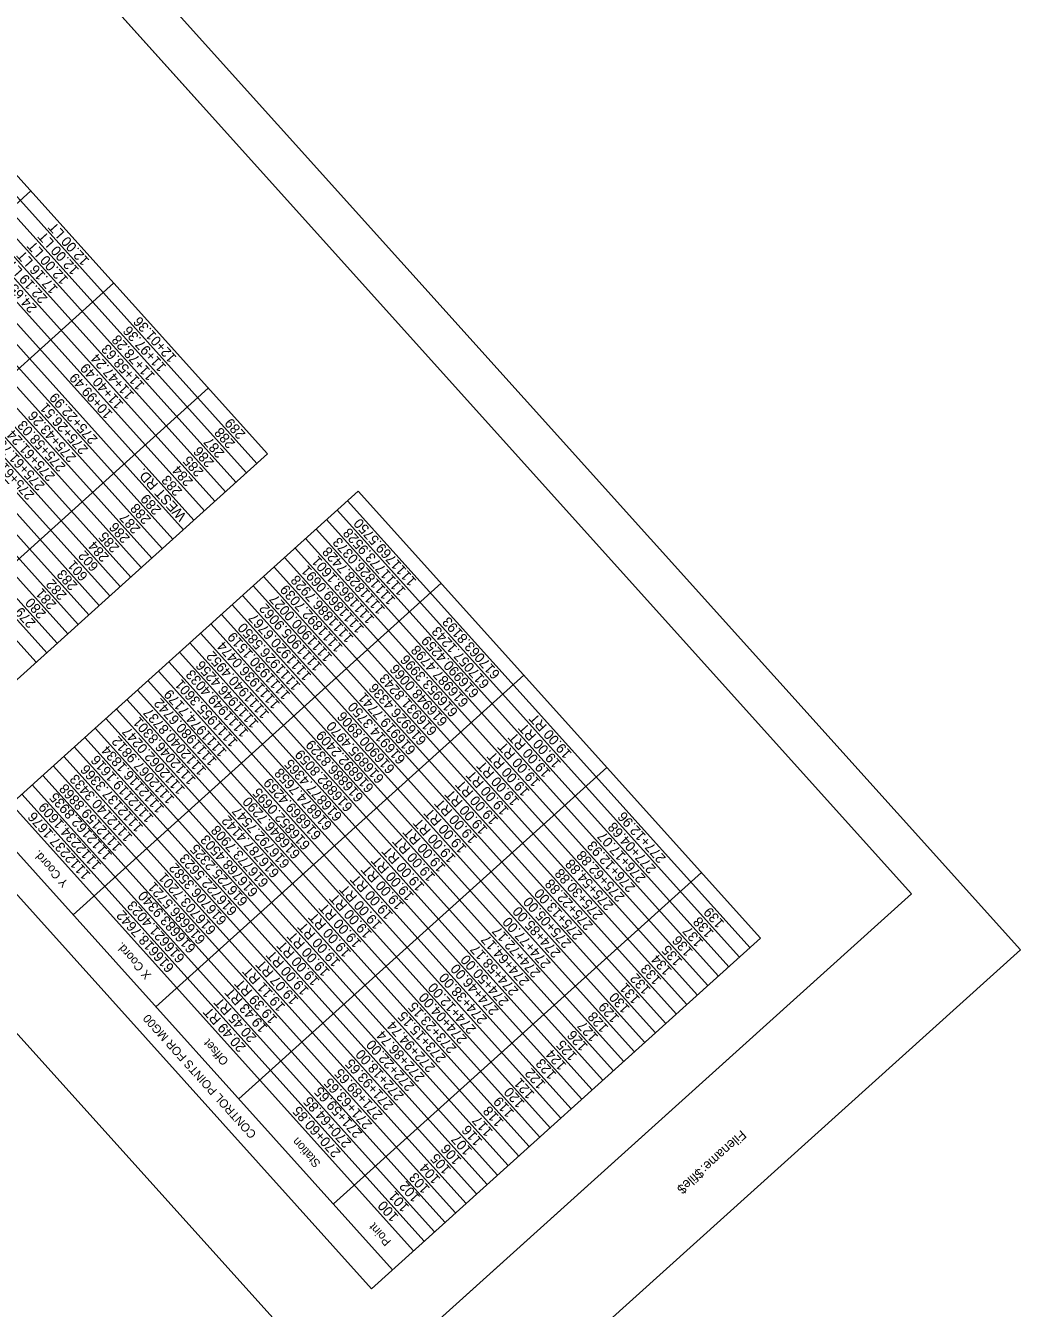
# Model space of a CAD drawing. Extents: x 1111534 to 1112511, y 616515 to 617559.
# Drawn here: x 1112159.5 to 1112511, y 616756 to 617209.1 of the extents above; entities that cross this region are included whole.
import ezdxf

# ---------------------------------------------------------------- set-up
doc = ezdxf.new("R2010")
doc.units = 0
for name, color, linetype in [('ANNOTATION', 7, 'Continuous'), ('BORDER', 7, 'Continuous'), ('CLIPS', 7, 'Continuous'), ('H_V CONTROLS', 7, 'Continuous'), ('PLOT BOUNDARY', 7, 'Continuous')]:
    doc.layers.add(name, color=color, linetype=linetype)

msp = doc.modelspace()

# ---------------------------------------------------------------- linework, layer by layer
at = {"layer": 'BORDER'}
for p, q in [((1112472.55, 616902.44), (1111937.25, 617496.96)), ((1112082.4, 616551.15), (1112472.55, 616902.44))]:
    msp.add_line(p, q, dxfattribs=at)
at = {"layer": 'CLIPS'}
msp.add_lwpolyline([(1112472.55, 616902.44), (1111970.7, 617459.8), (1111771.54, 617280.48), (1112273.39, 616723.12)], close=True, dxfattribs=at)
at = {"layer": 'H_V CONTROLS'}
for p, q in [((1112244.92, 617057.82), (1112102.73, 617215.74)), ((1112241.2, 617054.48), (1112099.01, 617212.4)), ((1112233.77, 617047.79), (1112091.58, 617205.71)), ((1112237.49, 617051.13), (1112095.3, 617209.05)), ((1112230.06, 617044.44), (1112087.87, 617202.36)), ((1112226.34, 617041.1), (1112084.15, 617199.01)), ((1112218.91, 617034.4), (1112076.72, 617192.32)), ((1112222.62, 617037.75), (1112080.43, 617195.67)), ((1112215.19, 617031.06), (1112073, 617188.98)), ((1112207.76, 617024.37), (1112065.57, 617182.29)), ((1112211.48, 617027.71), (1112069.29, 617185.63)), ((1112204.05, 617021.02), (1112061.86, 617178.94)), ((1112200.33, 617017.68), (1112058.14, 617175.59)), ((1112192.9, 617010.99), (1112050.71, 617168.9)), ((1112196.61, 617014.33), (1112054.42, 617172.25)), ((1112189.18, 617007.64), (1112046.99, 617165.56)), ((1112185.47, 617004.29), (1112043.28, 617162.21)), ((1112178.04, 616997.6), (1112035.85, 617155.52)), ((1112181.75, 617000.95), (1112039.56, 617158.87)), ((1112174.32, 616994.26), (1112032.13, 617152.18)), ((1112042.37, 617043.66), (1112161.28, 617150.72)), ((1112170.6, 616990.91), (1112028.41, 617148.83)), ((1112163.17, 616984.22), (1112020.98, 617142.14)), ((1112166.89, 616987.57), (1112024.7, 617145.48)), ((1112071.65, 617011.14), (1112190.55, 617118.2)), ((1112105.11, 616973.99), (1112224.01, 617081.05)), ((1112118.58, 616944.07), (1112244.92, 617057.82)), ((1112139.49, 616920.85), (1112276.98, 617044.64)), ((1112419.17, 616886.72), (1112276.98, 617044.64)), ((1112419.17, 616886.72), (1112276.98, 617044.64)), ((1112411.73, 616880.03), (1112269.54, 617037.95)), ((1112415.45, 616883.37), (1112273.26, 617041.29)), ((1112408.02, 616876.68), (1112265.83, 617034.6)), ((1112404.3, 616873.34), (1112262.11, 617031.26)), ((1112396.87, 616866.65), (1112254.68, 617024.56)), ((1112400.59, 616869.99), (1112258.4, 617027.91)), ((1112393.16, 616863.3), (1112250.97, 617021.22)), ((1112385.72, 616856.61), (1112243.53, 617014.53)), ((1112389.44, 616859.95), (1112247.25, 617017.87)), ((1112176.2, 616895.03), (1112306.25, 617012.13)), ((1112382.01, 616853.26), (1112239.82, 617011.18)), ((1112378.29, 616849.92), (1112236.1, 617007.84)), ((1112370.86, 616843.23), (1112228.67, 617001.14)), ((1112374.58, 616846.57), (1112232.39, 617004.49)), ((1112367.15, 616839.88), (1112224.96, 616997.8)), ((1112363.43, 616836.54), (1112221.24, 616994.45)), ((1112356, 616829.84), (1112213.81, 616987.76)), ((1112359.71, 616833.19), (1112217.52, 616991.11)), ((1112352.28, 616826.5), (1112210.09, 616984.42)), ((1112205.47, 616862.52), (1112335.53, 616979.61)), ((1112348.57, 616823.15), (1112206.38, 616981.07)), ((1112341.14, 616816.46), (1112198.95, 616974.38)), ((1112344.85, 616819.81), (1112202.66, 616977.73)), ((1112337.42, 616813.12), (1112195.23, 616971.03)), ((1112333.7, 616809.77), (1112191.51, 616967.69)), ((1112326.27, 616803.08), (1112184.08, 616961)), ((1112329.99, 616806.42), (1112187.8, 616964.34)), ((1112322.56, 616799.73), (1112180.37, 616957.65)), ((1112318.84, 616796.39), (1112176.65, 616954.31)), ((1112311.41, 616789.7), (1112169.22, 616947.61)), ((1112315.13, 616793.04), (1112172.94, 616950.96)), ((1112234.75, 616830), (1112364.8, 616947.1)), ((1112307.69, 616786.35), (1112165.5, 616944.27)), ((1112300.26, 616779.66), (1112158.07, 616937.58)), ((1112303.98, 616783), (1112161.79, 616940.92)), ((1112296.55, 616776.31), (1112154.36, 616934.23)), ((1112289.12, 616769.62), (1112146.93, 616927.54)), ((1112281.68, 616762.93), (1112139.49, 616920.85)), ((1112268.21, 616792.85), (1112398.26, 616909.94)), ((1112281.68, 616762.93), (1112419.17, 616886.72))]:
    msp.add_line(p, q, dxfattribs=at)
at = {"layer": 'PLOT BOUNDARY'}
msp.add_lwpolyline([(1112510.99, 616882.61), (1111942.23, 617514.28), (1111533.5, 617146.26), (1112102.26, 616514.59)], close=True, dxfattribs=at)

# ---------------------------------------------------------------- texts
at = {"layer": 'ANNOTATION'}
for s, height, p in [('12.00 LT', 3.516, (1112182.17, 617126.24)), ('12.00 LT', 3.516, (1112174.76, 617119.57)), ('12.00 LT', 3.516, (1112178.52, 617122.95)), ('17.16 LT', 3.516, (1112171.07, 617116.25)), ('22.19 LT', 3.516, (1112167.38, 617112.92)), ('24.65 LT', 3.516, (1112163.63, 617109.54)), ('12+01.36', 3.516, (1112213, 617092)), ('11+97.36', 3.516, (1112209.35, 617088.71)), ('11+58.63', 3.516, (1112201.69, 617082.24)), ('11+78.28', 3.516, (1112205.38, 617085.56)), ('11+47.24', 3.516, (1112198.01, 617078.92)), ('11+40.49', 3.516, (1112194.25, 617075.54)), ('10+99.49', 3.516, (1112190.43, 617072.1)), ('275+22.99', 3.516, (1112185.11, 617063.17)), ('275+26.51', 3.516, (1112181.73, 617059.57)), ('275+58.03', 3.516, (1112173.8, 617053.41)), ('275+43.26', 3.516, (1112177.51, 617056.75)), ('289', 3.516, (1112237.35, 617064.96)), ('275+61.24', 3.516, (1112170.08, 617050.06)), ('288', 3.516, (1112233.69, 617061.67)), ('275+61.73', 3.516, (1112166.43, 617046.77)), ('286', 3.516, (1112226.25, 617054.97)), ('287', 3.516, (1112229.94, 617058.29)), ('275+61.43', 3.45, (1112162.74, 617043.45)), ('285', 3.516, (1112222.56, 617051.64)), ('WEST RD.', 3.516, (1112216.49, 617036.01)), ('284', 3.516, (1112218.81, 617048.26)), ('283', 3.516, (1112214.99, 617044.83)), ('289', 3.516, (1112207.61, 617038.18)), ('288', 3.516, (1112203.96, 617034.89)), ('286', 3.516, (1112196.51, 617028.19)), ('287', 3.516, (1112200.22, 617031.53)), ('1111769.5750', 3.5156, (1112297.78, 617013.03)), ('285', 3.516, (1112192.79, 617024.84)), ('1111826.0373', 3.5156, (1112290.37, 617006.36)), ('1111773.9528', 3.5156, (1112294.03, 617009.65)), ('602', 3.45, (1112185.45, 617018.23)), ('284', 3.516, (1112189.14, 617021.55)), ('1111828.7428', 3.5156, (1112286.69, 617003.04)), ('601', 3.45, (1112181.66, 617014.81)), ('1111863.1601', 3.5156, (1112282.93, 616999.66)), ('283', 3.516, (1112178, 617011.52)), ('1111886.7928', 3.5156, (1112275.52, 616992.99)), ('1111869.0691', 3.5156, (1112279.24, 616996.34)), ('281', 3.516, (1112170.53, 617004.79)), ('282', 3.516, (1112174.19, 617008.09)), ('1111892.7039', 3.5156, (1112271.78, 616989.62)), ('280', 3.516, (1112166.87, 617001.5)), ('1111900.0027', 3.5156, (1112268.03, 616986.24)), ('279', 3.516, (1112163.22, 616998.21)), ('1111920.6767', 3.5156, (1112260.64, 616979.58)), ('1111905.9062', 3.5156, (1112264.39, 616982.96)), ('1111926.5850', 3.5156, (1112256.82, 616976.14)), ('617057.1243', 3.5156, (1112323.6, 616976.81)), ('617063.8193', 3.5156, (1112327.35, 616980.19)), ('1111930.1519', 3.5156, (1112253.19, 616972.88)), ('616990.4259', 3.5156, (1112319.94, 616973.52)), ('1111940.4952', 3.5156, (1112245.72, 616966.15)), ('1111936.0474', 3.5156, (1112249.54, 616969.59)), ('616987.4798', 3.5156, (1112316.25, 616970.2)), ('1111946.4256', 3.5156, (1112242, 616962.8)), ('616948.0066', 3.5156, (1112308.81, 616963.5)), ('616953.3996', 3.5156, (1112312.5, 616966.82)), ('1111955.3601', 3.5156, (1112234.62, 616956.16)), ('1111949.4033', 3.5156, (1112238.44, 616959.6)), ('616931.8243', 3.5156, (1112305.09, 616960.15)), ('1111974.7179', 3.5156, (1112230.74, 616952.66)), ('616926.4336', 3.5156, (1112301.35, 616956.78)), ('1111980.6742', 3.5156, (1112227.21, 616949.49)), ('616914.3750', 3.5156, (1112293.96, 616950.12)), ('616919.7741', 3.5156, (1112297.6, 616953.4)), ('1112046.8301', 3.5156, (1112219.8, 616942.81)), ('1112040.8737', 3.5156, (1112223.49, 616946.13)), ('616900.8906', 3.5156, (1112290.2, 616946.74)), ('19.00 RT', 3.516, (1112352.65, 616952.09)), ('1112062.0247', 3.5156, (1112216.01, 616939.4)), ('616895.4970', 3.5156, (1112286.39, 616943.31)), ('19.00 RT', 3.516, (1112348.9, 616948.71)), ('1112067.9812', 3.5156, (1112212.29, 616936.05)), ('616886.8329', 3.5156, (1112279.11, 616936.75)), ('616892.2409', 3.5156, (1112282.76, 616940.04)), ('19.00 RT', 3.516, (1112345.24, 616945.42)), ('1112119.1616', 3.5156, (1112204.9, 616929.4)), ('1112116.1834', 3.5156, (1112208.65, 616932.78)), ('616882.8059', 3.5156, (1112275.29, 616933.31)), ('19.00 RT', 3.516, (1112337.8, 616938.72)), ('19.00 RT', 3.516, (1112341.55, 616942.1)), ('1112137.3366', 3.5156, (1112201.21, 616926.07)), ('616874.7658', 3.5156, (1112268.01, 616926.76)), ('616877.4365', 3.5156, (1112271.57, 616929.96)), ('19.00 RT', 3.516, (1112334.11, 616935.4)), ('1112140.3433', 3.5156, (1112197.42, 616922.67)), ('616869.4259', 3.5156, (1112264.19, 616923.32)), ('19.00 RT', 3.516, (1112326.65, 616928.68)), ('19.00 RT', 3.516, (1112330.39, 616932.05)), ('1112162.8935', 3.5156, (1112190.26, 616916.21)), ('1112159.8868', 3.5156, (1112193.7, 616919.31)), ('616852.0695', 3.5156, (1112260.3, 616919.82)), ('19.00 RT', 3.516, (1112322.9, 616925.3)), ('1112234.1609', 3.5156, (1112186.41, 616912.75)), ('616846.7290', 3.5156, (1112256.78, 616916.65)), ('19.00 RT', 3.516, (1112319.26, 616922.03)), ('1112237.1676', 3.5156, (1112182.62, 616909.34)), ('616787.4142', 3.5156, (1112249.37, 616909.97)), ('616792.7547', 3.5156, (1112253.06, 616913.3)), ('19.00 RT', 3.516, (1112311.69, 616915.21)), ('19.00 RT', 3.516, (1112315.5, 616918.65)), ('277+12.96', 3.516, (1112385.92, 616915.15)), ('616773.7908', 3.5156, (1112245.58, 616906.57)), ('19.00 RT', 3.516, (1112308.06, 616911.94)), ('277+04.68', 3.516, (1112382.44, 616911.46)), ('616725.2325', 3.5156, (1112238.22, 616899.94)), ('616768.4503', 3.5156, (1112241.86, 616903.21)), ('19.00 RT', 3.516, (1112304.41, 616908.65)), ('276+12.93', 3.516, (1112375.1, 616904.85)), ('276+17.07', 3.516, (1112378.79, 616908.17)), ('616722.5623', 3.5156, (1112234.47, 616896.56)), ('19.00 RT', 3.516, (1112296.87, 616901.86)), ('19.00 RT', 3.516, (1112300.59, 616905.21)), ('275+62.88', 3.516, (1112371.34, 616901.47)), ('616706.3582', 3.5156, (1112230.78, 616893.24)), ('19.00 RT', 3.516, (1112293.31, 616898.66)), ('275+30.88', 3.516, (1112363.66, 616895.1)), ('275+54.88', 3.516, (1112367.38, 616898.45)), ('616686.5721', 3.5156, (1112223.27, 616886.48)), ('616703.7201', 3.5156, (1112226.99, 616889.83)), ('19.00 RT', 3.516, (1112289.49, 616895.22)), ('275+22.88', 3.516, (1112360.2, 616891.43)), ('616683.9340', 3.5156, (1112219.83, 616883.37)), ('19.00 RT', 3.516, (1112282.08, 616888.55)), ('19.00 RT', 3.516, (1112285.6, 616891.72)), ('275+13.00', 3.516, (1112356.44, 616888.05)), ('616618.7642', 3.5156, (1112212.19, 616876.5)), ('616621.4023', 3.5156, (1112215.97, 616879.91)), ('19.00 RT', 3.516, (1112278.36, 616885.2)), ('274+85.00', 3.516, (1112348.77, 616881.7)), ('275+05.00', 3.516, (1112352.53, 616885.08)), ('139', 3.516, (1112406.59, 616892.19)), ('19.00 RT', 3.516, (1112274.67, 616881.88)), ('274+77.00', 3.516, (1112345.23, 616877.95)), ('138', 3.516, (1112402.84, 616888.81)), ('19.00 RT', 3.516, (1112267.16, 616875.12)), ('19.00 RT', 3.516, (1112270.88, 616878.47)), ('274+72.17', 3.516, (1112341.6, 616874.69)), ('137', 3.516, (1112399.18, 616885.51)), ('19.00 RT', 3.516, (1112263.52, 616871.84)), ('274+58.17', 3.516, (1112333.85, 616868.27)), ('274+64.17', 3.516, (1112337.67, 616871.71)), ('135', 3.516, (1112391.74, 616878.81)), ('136', 3.516, (1112395.49, 616882.19)), ('19.07 RT', 3.516, (1112256.08, 616865.14)), ('19.00 RT', 3.516, (1112259.77, 616868.46)), ('274+50.00', 3.516, (1112330.41, 616864.61)), ('134', 3.516, (1112388.05, 616875.49)), ('19.11 RT', 3.516, (1112251.39, 616862.73)), ('274+38.00', 3.516, (1112322.76, 616858.27)), ('274+46.00', 3.516, (1112326.85, 616861.41)), ('132', 3.516, (1112380.59, 616868.78)), ('133', 3.516, (1112384.33, 616872.14)), ('19.39 RT', 3.516, (1112248.57, 616858.38)), ('274+12.00', 3.516, (1112318.87, 616854.78)), ('131', 3.516, (1112376.84, 616865.4)), ('20.45 RT', 3.516, (1112241.27, 616851.81)), ('19.43 RT', 3.516, (1112245.13, 616855.28)), ('274+04.00', 3.516, (1112315.62, 616851.3)), ('130', 3.516, (1112373.2, 616862.12)), ('20.49 RT', 3.516, (1112237.49, 616848.4)), ('273+15.15', 3.516, (1112308.21, 616844.62)), ('273+23.15', 3.516, (1112311.9, 616847.94)), ('128', 3.516, (1112365.63, 616855.3)), ('129', 3.516, (1112369.45, 616858.74)), ('272+94.74', 3.516, (1112304.42, 616841.21)), ('127', 3.516, (1112362, 616852.04)), ('272+86.74', 3.516, (1112300.7, 616837.86)), ('126', 3.516, (1112358.35, 616848.74)), ('272+18.00', 3.516, (1112293.31, 616831.21)), ('272+22.00', 3.516, (1112297.06, 616834.59)), ('124', 3.516, (1112350.81, 616841.96)), ('125', 3.516, (1112354.53, 616845.31)), ('271+93.65', 3.516, (1112289.62, 616827.88)), ('123', 3.516, (1112347.25, 616838.75)), ('271+89.65', 3.516, (1112285.83, 616824.47)), ('122', 3.516, (1112343.43, 616835.31)), ('271+59.65', 3.516, (1112278.67, 616818.02)), ('271+63.65', 3.516, (1112282.11, 616821.12)), ('120', 3.516, (1112336.02, 616828.64)), ('121', 3.516, (1112339.54, 616831.82)), ('270+64.85', 3.516, (1112274.82, 616814.56)), ('119', 3.516, (1112332.3, 616825.29)), ('270+60.85', 3.516, (1112271.03, 616811.15)), ('118', 3.516, (1112328.61, 616821.97)), ('116', 3.516, (1112321.1, 616815.21)), ('117', 3.516, (1112324.82, 616818.56)), ('107', 3.516, (1112317.46, 616811.93)), ('106', 3.516, (1112313.71, 616808.55)), ('104', 3.516, (1112306.23, 616801.82)), ('105', 3.516, (1112310.02, 616805.23)), ('103', 3.516, (1112302.51, 616798.47)), ('101', 3.516, (1112295.22, 616791.9)), ('102', 3.516, (1112299.07, 616795.37)), ('100', 3.516, (1112291.43, 616788.49))]:
    msp.add_text(s, height=height, rotation=132, dxfattribs=at).set_placement(p)
at = {"layer": 'BORDER'}
for s, p in [('Filename:', (1112412.31, 616819.17)), ('$file$', (1112397.34, 616805.7))]:
    msp.add_text(s, height=3.348, rotation=222, dxfattribs=at).set_placement(p)
at = {"layer": 'H_V CONTROLS'}
for s, p in [('Y Coord.', (1112174.73, 616906.37)), ('X Coord.', (1112204.01, 616873.86)), ('CONTROL POINTS FOR MG00', (1112241.2, 616817.61)), ('Offset', (1112231.39, 616843.44)), ('Station', (1112263.91, 616807.33)), ('Point', (1112288.81, 616779.68))]:
    msp.add_text(s, height=3, rotation=132, dxfattribs=at).set_placement(p)

doc.saveas('drawing.dxf')
